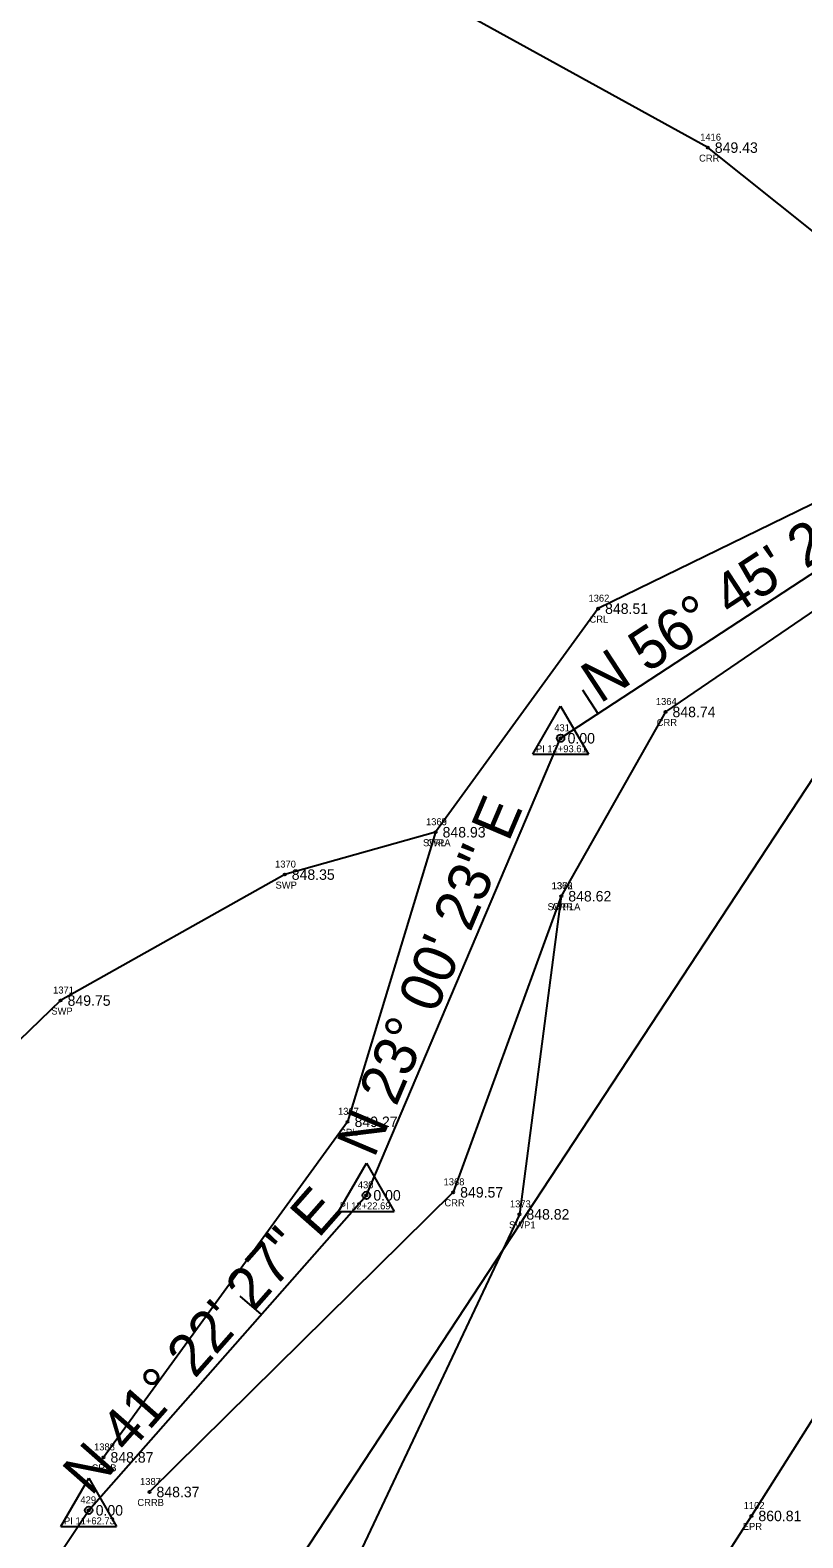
# Model space of a CAD drawing. Extents: x 1393163 to 1398407, y 1072670 to 1074651.
# Drawn here: x 1395719 to 1395829.2, y 1073833.3 to 1074048.6 of the extents above; entities that cross this region are included whole.
import ezdxf

# ---------------------------------------------------------------- set-up
doc = ezdxf.new("R2010")
doc.units = 0
for name, color, linetype in [('RD_EX_H2O', 7, 'Continuous'), ('RD_EX_H2O_txCode', 7, 'Continuous'), ('RD_EX_Road', 7, 'Continuous'), ('RD_EX_Road_txCode', 7, 'Continuous'), ('RD_EX_TX_H2O_ELEV', 7, 'Continuous'), ('RD_EX_TX_Road_ELEV', 7, 'Continuous'), ('RD_EX_VEG', 7, 'Continuous'), ('RD_HC_Cl', 7, 'Continuous'), ('RD_HC_Data', 7, 'Continuous'), ('RD_HC_Data_Tic', 7, 'Continuous'), ('RD_HC_Survey_ELEV', 7, 'Continuous'), ('RD_HC_txCode', 7, 'Continuous'), ('RD_SMD_Locator', 7, 'Continuous')]:
    doc.layers.add(name, color=color, linetype=linetype)

msp = doc.modelspace()

# ---------------------------------------------------------------- linework, layer by layer
at = {"layer": 'RD_EX_H2O'}
for points in [[(1395860.9, 1073995.76), (1395815.67, 1074031.86), (1395776.21, 1074053.68), (1395741.83, 1074102.21), (1395737.14, 1074094.97), (1395730.93, 1074079.84), (1395706.27, 1074079.36), (1395688.76, 1074107.43)], [(1395860.9, 1073995.76), (1395800.01, 1073966.01), (1395776.82, 1073934.08), (1395764.26, 1073892.72), (1395729.42, 1073844.79)], [(1395867.11, 1073990.5), (1395809.63, 1073951.26), (1395794.76, 1073924.94), (1395779.33, 1073882.65), (1395735.99, 1073839.85)], [(1395776.82, 1073934.08), (1395755.29, 1073928.03), (1395723.3, 1073910.04), (1395687.91, 1073875.83), (1395647.24, 1073859.28), (1395617.21, 1073860.94), (1395608.35, 1073835.94), (1395582.11, 1073791.21), (1395612.65, 1073738.77), (1395640.23, 1073718.58), (1395621.2, 1073699.63)], [(1395794.76, 1073924.94), (1395788.78, 1073879.5), (1395765.52, 1073830.16), (1395736.34, 1073781.19), (1395672.02, 1073727.34), (1395621.2, 1073699.63)]]:
    msp.add_lwpolyline(points, dxfattribs=at)
at = {"layer": 'RD_EX_Road'}
msp.add_lwpolyline([(1395869.55, 1073911.71), (1395848.71, 1073878.81), (1395821.89, 1073836.43), (1395795.02, 1073794.57), (1395768.15, 1073753.29), (1395739.4, 1073711.73), (1395711.25, 1073671.91), (1395680.67, 1073632.3), (1395648.91, 1073595.47), (1395613.89, 1073559.5), (1395578.15, 1073528.43), (1395538.64, 1073499.26)], dxfattribs=at)
at = {"layer": 'RD_EX_VEG'}
msp.add_lwpolyline([(1396352.77, 1074466.81), (1396307.45, 1074411.54), (1396264.81, 1074389.13), (1396223.65, 1074377.38), (1396189.41, 1074374.79), (1396152.48, 1074363.91), (1396104.93, 1074328.72), (1396084.67, 1074294.89), (1396058.15, 1074258), (1396032.64, 1074208.26), (1395942.76, 1074111.4), (1395907.95, 1074076.23), (1395890.22, 1074043.32), (1395830.78, 1073942), (1395722.32, 1073776.86), (1395650.71, 1073693.74), (1395598.01, 1073628.59), (1395527.38, 1073544.13)], dxfattribs=at)
at = {"layer": 'RD_HC_Cl'}
for p, q in [((1395794.66, 1073947.5), (1395856.32, 1073987.92)), ((1395766.94, 1073882.22), (1395794.66, 1073947.5)), ((1395727.31, 1073837.23), (1395766.94, 1073882.22)), ((1395648.82, 1073719.51), (1395727.31, 1073837.23))]:
    msp.add_line(p, q, dxfattribs=at)
at = {"layer": 'RD_HC_Data'}
for p, q in [((1395790.69, 1073945.21), (1395794.66, 1073952.09)), ((1395794.66, 1073952.09), (1395798.63, 1073945.21)), ((1395790.69, 1073945.21), (1395798.63, 1073945.21)), ((1395762.97, 1073879.93), (1395766.95, 1073886.81)), ((1395766.95, 1073886.81), (1395770.91, 1073879.93)), ((1395762.97, 1073879.93), (1395770.91, 1073879.93)), ((1395723.34, 1073834.93), (1395727.31, 1073841.81)), ((1395727.31, 1073841.81), (1395731.28, 1073834.93)), ((1395723.34, 1073834.93), (1395731.28, 1073834.93))]:
    msp.add_line(p, q, dxfattribs=at)
for centre in [(1395794.66, 1073947.5), (1395766.94, 1073882.22), (1395727.31, 1073837.23)]:
    msp.add_circle(centre, 0.529, dxfattribs=at)
at = {"layer": 'RD_HC_Data_Tic'}
for p, q in [((1395800, 1073951.01), (1395797.81, 1073954.35)), ((1395751.95, 1073865.2), (1395748.94, 1073867.84))]:
    msp.add_line(p, q, dxfattribs=at)
at = {"layer": 'RD_SMD_Locator'}
for centre in [(1395815.67, 1074031.86), (1395800.01, 1073966.01), (1395809.63, 1073951.26), (1395794.66, 1073947.5), (1395776.82, 1073934.08), (1395776.82, 1073934.08), (1395755.29, 1073928.03), (1395794.76, 1073924.94), (1395794.76, 1073924.94), (1395723.3, 1073910.04), (1395764.26, 1073892.72), (1395779.33, 1073882.65), (1395766.94, 1073882.22), (1395788.78, 1073879.5), (1395729.42, 1073844.79), (1395735.99, 1073839.85), (1395727.31, 1073837.23), (1395821.89, 1073836.43)]:
    msp.add_circle(centre, 0.15, dxfattribs=at)

# ---------------------------------------------------------------- texts
at = {"layer": 'RD_EX_H2O_txCode'}
for s, p in [('1416', (1395814.58, 1074032.86)), ('CRR', (1395814.42, 1074029.86)), ('1362', (1395798.64, 1073967.01)), ('CRL', (1395798.78, 1073964.01)), ('1364', (1395808.26, 1073952.26)), ('CRR', (1395808.38, 1073949.26)), ('1365', (1395775.45, 1073935.08)), ('1369', (1395775.45, 1073935.08)), ('SWPA', (1395775.02, 1073932.08)), ('CRL', (1395775.6, 1073932.08)), ('1370', (1395753.91, 1073929.03)), ('SWP', (1395753.98, 1073926.03)), ('1366', (1395793.37, 1073925.94)), ('1372', (1395793.42, 1073925.94)), ('SWP1A', (1395792.8, 1073922.94)), ('CRR', (1395793.51, 1073922.94)), ('1371', (1395722.23, 1073911.04)), ('SWP', (1395721.98, 1073908.04)), ('1367', (1395762.89, 1073893.72)), ('CRL', (1395763.03, 1073890.72)), ('1368', (1395777.96, 1073883.65)), ('CRR', (1395778.08, 1073880.65)), ('1373', (1395787.43, 1073880.5)), ('SWP1', (1395787.3, 1073877.5)), ('1388', (1395728.07, 1073845.79)), ('CRLB', (1395727.72, 1073842.79)), ('1387', (1395734.64, 1073840.85)), ('CRRB', (1395734.26, 1073837.85))]:
    msp.add_text(s, height=1, dxfattribs=at).set_placement(p)
at = {"layer": 'RD_EX_Road_txCode'}
for s, p in [('1102', (1395820.79, 1073837.43)), ('EPR', (1395820.66, 1073834.43))]:
    msp.add_text(s, height=1, dxfattribs=at).set_placement(p)
at = {"layer": 'RD_EX_TX_H2O_ELEV'}
for s, p in [('849.43', (1395816.67, 1074031.11)), ('848.51', (1395801.01, 1073965.26)), ('848.74', (1395810.63, 1073950.51)), ('848.93', (1395777.82, 1073933.33)), ('848.93', (1395777.82, 1073933.33)), ('848.35', (1395756.29, 1073927.28)), ('848.62', (1395795.76, 1073924.19)), ('848.62', (1395795.76, 1073924.19)), ('849.75', (1395724.3, 1073909.29)), ('849.27', (1395765.26, 1073891.97)), ('849.57', (1395780.33, 1073881.9)), ('848.82', (1395789.78, 1073878.75)), ('848.87', (1395730.42, 1073844.04)), ('848.37', (1395736.99, 1073839.1))]:
    msp.add_text(s, height=1.5, dxfattribs=at).set_placement(p)
at = {"layer": 'RD_EX_TX_Road_ELEV'}
msp.add_text('860.81', height=1.5, dxfattribs=at).set_placement((1395822.89, 1073835.68))
at = {"layer": 'RD_HC_Data'}
for s, rotation, p in [('N 56%%d 45\' 24" E', 33.2434, (1395800.27, 1073952.37)), ('N 23%%d 00\' 23" E', 66.9937, (1395768.06, 1073887.4)), ('N 41%%d 22\' 27" E', 48.6259, (1395727.66, 1073839.13))]:
    msp.add_text(s, height=6, rotation=rotation, dxfattribs=at).set_placement(p)
at = {"layer": 'RD_HC_Survey_ELEV'}
for p in [(1395795.66, 1073946.75), (1395767.94, 1073881.47), (1395728.31, 1073836.48)]:
    msp.add_text('0.00', height=1.5, dxfattribs=at).set_placement(p)
at = {"layer": 'RD_HC_txCode'}
for s, p in [('431', (1395793.76, 1073948.5)), ('PI 12+93.61', (1395791.14, 1073945.5)), ('430', (1395765.72, 1073883.22)), ('PI 12+22.69', (1395763.14, 1073880.22)), ('429', (1395726.13, 1073838.23)), ('PI 11+62.73', (1395723.79, 1073835.23))]:
    msp.add_text(s, height=1, dxfattribs=at).set_placement(p)

doc.saveas('drawing.dxf')
